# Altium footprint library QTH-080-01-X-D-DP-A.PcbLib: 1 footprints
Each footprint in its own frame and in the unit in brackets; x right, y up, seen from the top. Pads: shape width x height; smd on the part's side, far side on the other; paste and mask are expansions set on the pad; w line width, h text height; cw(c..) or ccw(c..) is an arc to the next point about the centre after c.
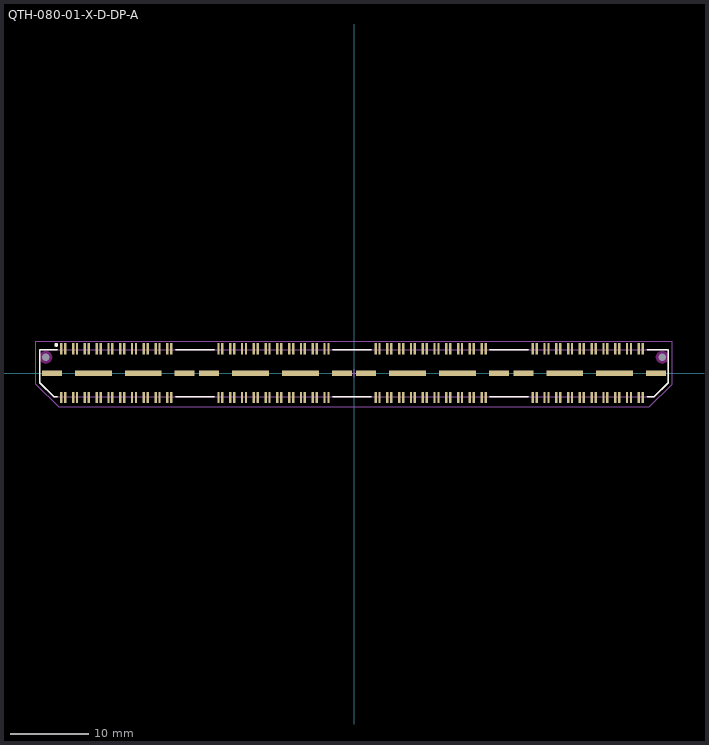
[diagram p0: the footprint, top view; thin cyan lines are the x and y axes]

## QTH-080-01-X-D-DP-A [mm] "0.50mm pitch, 160 pin, high speed terminal strip; differential"
height 4.27
pads (178):
  rect 0.3x1.45 smd mask+0: 1(-37.25,3.09) 2(-37.25,-3.09) 3(-36.75,3.09) 4(-36.75,-3.09) 5(-35.75,3.09) 6(-35.75,-3.09) 7(-35.25,3.09) 8(-35.25,-3.09) 9(-34.25,3.09) 10(-34.25,-3.09) 11(-33.75,3.09) 12(-33.75,-3.09) 13(-32.75,3.09) 14(-32.75,-3.09) 15(-32.25,3.09) 16(-32.25,-3.09) 17(-31.25,3.09) 18(-31.25,-3.09) 19(-30.75,3.09) 20(-30.75,-3.09) 21(-29.75,3.09) 22(-29.75,-3.09) 23(-29.25,3.09) 24(-29.25,-3.09) 25(-28.25,3.09) 26(-28.25,-3.09) 27(-27.75,3.09) 28(-27.75,-3.09) 29(-26.75,3.09) 30(-26.75,-3.09) 31(-26.25,3.09) 32(-26.25,-3.09) 33(-25.25,3.09) 34(-25.25,-3.09) 35(-24.75,3.09) 36(-24.75,-3.09) 37(-23.75,3.09) 38(-23.75,-3.09) 39(-23.25,3.09) 40(-23.25,-3.09) 41(-17.25,3.09) 42(-17.25,-3.09) 43(-16.75,3.09) 44(-16.75,-3.09) 45(-15.75,3.09) 46(-15.75,-3.09) 47(-15.25,3.09) 48(-15.25,-3.09) 49(-14.25,3.09) 50(-14.25,-3.09) 51(-13.75,3.09) 52(-13.75,-3.09) 53(-12.75,3.09) 54(-12.75,-3.09) 55(-12.25,3.09) 56(-12.25,-3.09) 57(-11.25,3.09) 58(-11.25,-3.09) 59(-10.75,3.09) 60(-10.75,-3.09) 61(-9.75,3.09) 62(-9.75,-3.09) 63(-9.25,3.09) 64(-9.25,-3.09) 65(-8.25,3.09) 66(-8.25,-3.09) 67(-7.75,3.09) 68(-7.75,-3.09) 69(-6.75,3.09) 70(-6.75,-3.09) 71(-6.25,3.09) 72(-6.25,-3.09) 73(-5.25,3.09) 74(-5.25,-3.09) 75(-4.75,3.09) 76(-4.75,-3.09) 77(-3.75,3.09) 78(-3.75,-3.09) 79(-3.25,3.09) 80(-3.25,-3.09) 81(2.75,3.09) 82(2.75,-3.09) 83(3.25,3.09) 84(3.25,-3.09) 85(4.25,3.09) 86(4.25,-3.09) 87(4.75,3.09) 88(4.75,-3.09) 89(5.75,3.09) 90(5.75,-3.09) 91(6.25,3.09) 92(6.25,-3.09) 93(7.25,3.09) 94(7.25,-3.09) 95(7.75,3.09) 96(7.75,-3.09) 97(8.75,3.09) 98(8.75,-3.09) 99(9.25,3.09) 100(9.25,-3.09) 101(10.25,3.09) 102(10.25,-3.09) 103(10.75,3.09) 104(10.75,-3.09) 105(11.75,3.09) 106(11.75,-3.09) 107(12.25,3.09) 108(12.25,-3.09) 109(13.25,3.09) 110(13.25,-3.09) 111(13.75,3.09) 112(13.75,-3.09) 113(14.75,3.09) 114(14.75,-3.09) 115(15.25,3.09) 116(15.25,-3.09) 117(16.25,3.09) 118(16.25,-3.09) 119(16.75,3.09) 120(16.75,-3.09) 121(22.75,3.09) 122(22.75,-3.09) 123(23.25,3.09) 124(23.25,-3.09) 125(24.25,3.09) 126(24.25,-3.09) 127(24.75,3.09) 128(24.75,-3.09) 129(25.75,3.09) 130(25.75,-3.09) 131(26.25,3.09) 132(26.25,-3.09) 133(27.25,3.09) 134(27.25,-3.09) 135(27.75,3.09) 136(27.75,-3.09) 137(28.75,3.09) 138(28.75,-3.09) 139(29.25,3.09) 140(29.25,-3.09) 141(30.25,3.09) 142(30.25,-3.09) 143(30.75,3.09) 144(30.75,-3.09) 145(31.75,3.09) 146(31.75,-3.09) 147(32.25,3.09) 148(32.25,-3.09) 149(33.25,3.09) 150(33.25,-3.09) 151(33.75,3.09) 152(33.75,-3.09) 153(34.75,3.09) 154(34.75,-3.09) 155(35.25,3.09) 156(35.25,-3.09) 157(36.25,3.09) 158(36.25,-3.09) 159(36.75,3.09) 160(36.75,-3.09)
  rect 2.55x0.65 smd mask+0: 161(-38.445,0) 164(-21.555,0) 165(-18.445,0) 168(-1.555,0) 169(1.555,0) 172(18.445,0) 173(21.555,0) 176(38.445,0)
  rect 4.7x0.65 smd mask+0: 162(-33.175,0) 163(-26.825,0) 166(-13.175,0) 167(-6.825,0) 170(6.825,0) 171(13.175,0) 174(26.825,0) 175(33.175,0)
  round 0.5 hole 1 unplated mask+0: 177(-39.24,2.03) 178(39.24,2.03)
Top Overlay:
  circle w0.25: c-37.9,3.6 r0.125
  lines w0.2: -37.8,-3 -38.2,-3 -40,-1.2 -40,3 -37.8,3 ; -22.7,-3 -17.8,-3 ; -22.7,3 -17.8,3 ; -2.7,-3 2.2,-3 ; -2.7,3 2.2,3 ; 17.3,-3 22.2,-3 ; 17.3,3 22.2,3 ; 37.3,-3 38.2,-3 40,-1.2 40,3 37.3,3
Keep-Out Layer:
  pour cut-out: 40.047,2.03 40.019,2.239 39.939,2.433 39.811,2.601 39.643,2.729 39.449,2.809 39.24,2.837 39.031,2.809 38.837,2.729 38.669,2.601 38.541,2.433 38.461,2.239 38.433,2.03 38.461,1.821 38.541,1.627 38.669,1.459 38.837,1.331 39.031,1.251 39.24,1.223 39.449,1.251 39.643,1.331 39.811,1.459 39.939,1.627 40.019,1.821
  pour cut-out: -38.433,2.03 -38.461,2.239 -38.541,2.433 -38.669,2.601 -38.837,2.729 -39.031,2.809 -39.24,2.837 -39.449,2.809 -39.643,2.729 -39.811,2.601 -39.939,2.433 -40.019,2.239 -40.047,2.03 -40.019,1.821 -39.939,1.627 -39.811,1.459 -39.643,1.331 -39.449,1.251 -39.24,1.223 -39.031,1.251 -38.837,1.331 -38.669,1.459 -38.541,1.627 -38.461,1.821
Mechanical 12:
  lines w0.001: -40,-1.2 -40,3 40.001,3 40,-1.201 38.2,-3 -38.201,-3 -40,-1.2
Mechanical 13:
  lines w0.1: -40,-1.2 -40,3 40.001,3 40,-1.201 38.2,-3 -38.201,-3 -40,-1.2
  text ".Designator" at 0,-0.127 h1.52
Mechanical 15:
  lines w0.05: -0.5,0 0.5,0 ; 0,-0.5 0,0.5 ; -40.5,-1.4 -40.5,4.1 40.5,4.1 40.5,-1.4 37.6,-4.3 -37.6,-4.3 -40.5,-1.4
